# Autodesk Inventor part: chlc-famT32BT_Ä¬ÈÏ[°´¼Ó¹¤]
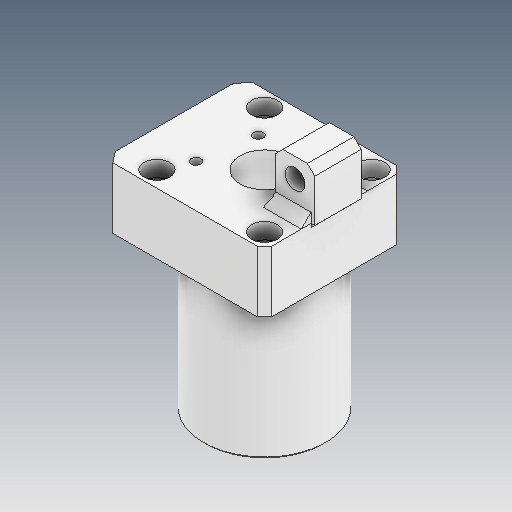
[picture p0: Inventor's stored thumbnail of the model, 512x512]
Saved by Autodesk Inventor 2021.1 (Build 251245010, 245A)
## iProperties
Created: 2021-05
Part Number: chlc-famT32BT_Ä¬ÈÏ[°´¼Ó¹¤]
Material: Ogólny
Document SubType Name: Modeling
Designer: user
Density: 1 g/cm^3
Appearance: Domyślna
Author: user
Revision Number: ÈÎºÎ
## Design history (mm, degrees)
feature "µ¹½Ç2" [ÊäÈë]
feature "ÊäÈë7"
feature "ÊäÈë8"
feature "ÊäÈë9"
node "Bryła1"
node "Bryła2"
node "Bryła3"
node "Bryła4"
